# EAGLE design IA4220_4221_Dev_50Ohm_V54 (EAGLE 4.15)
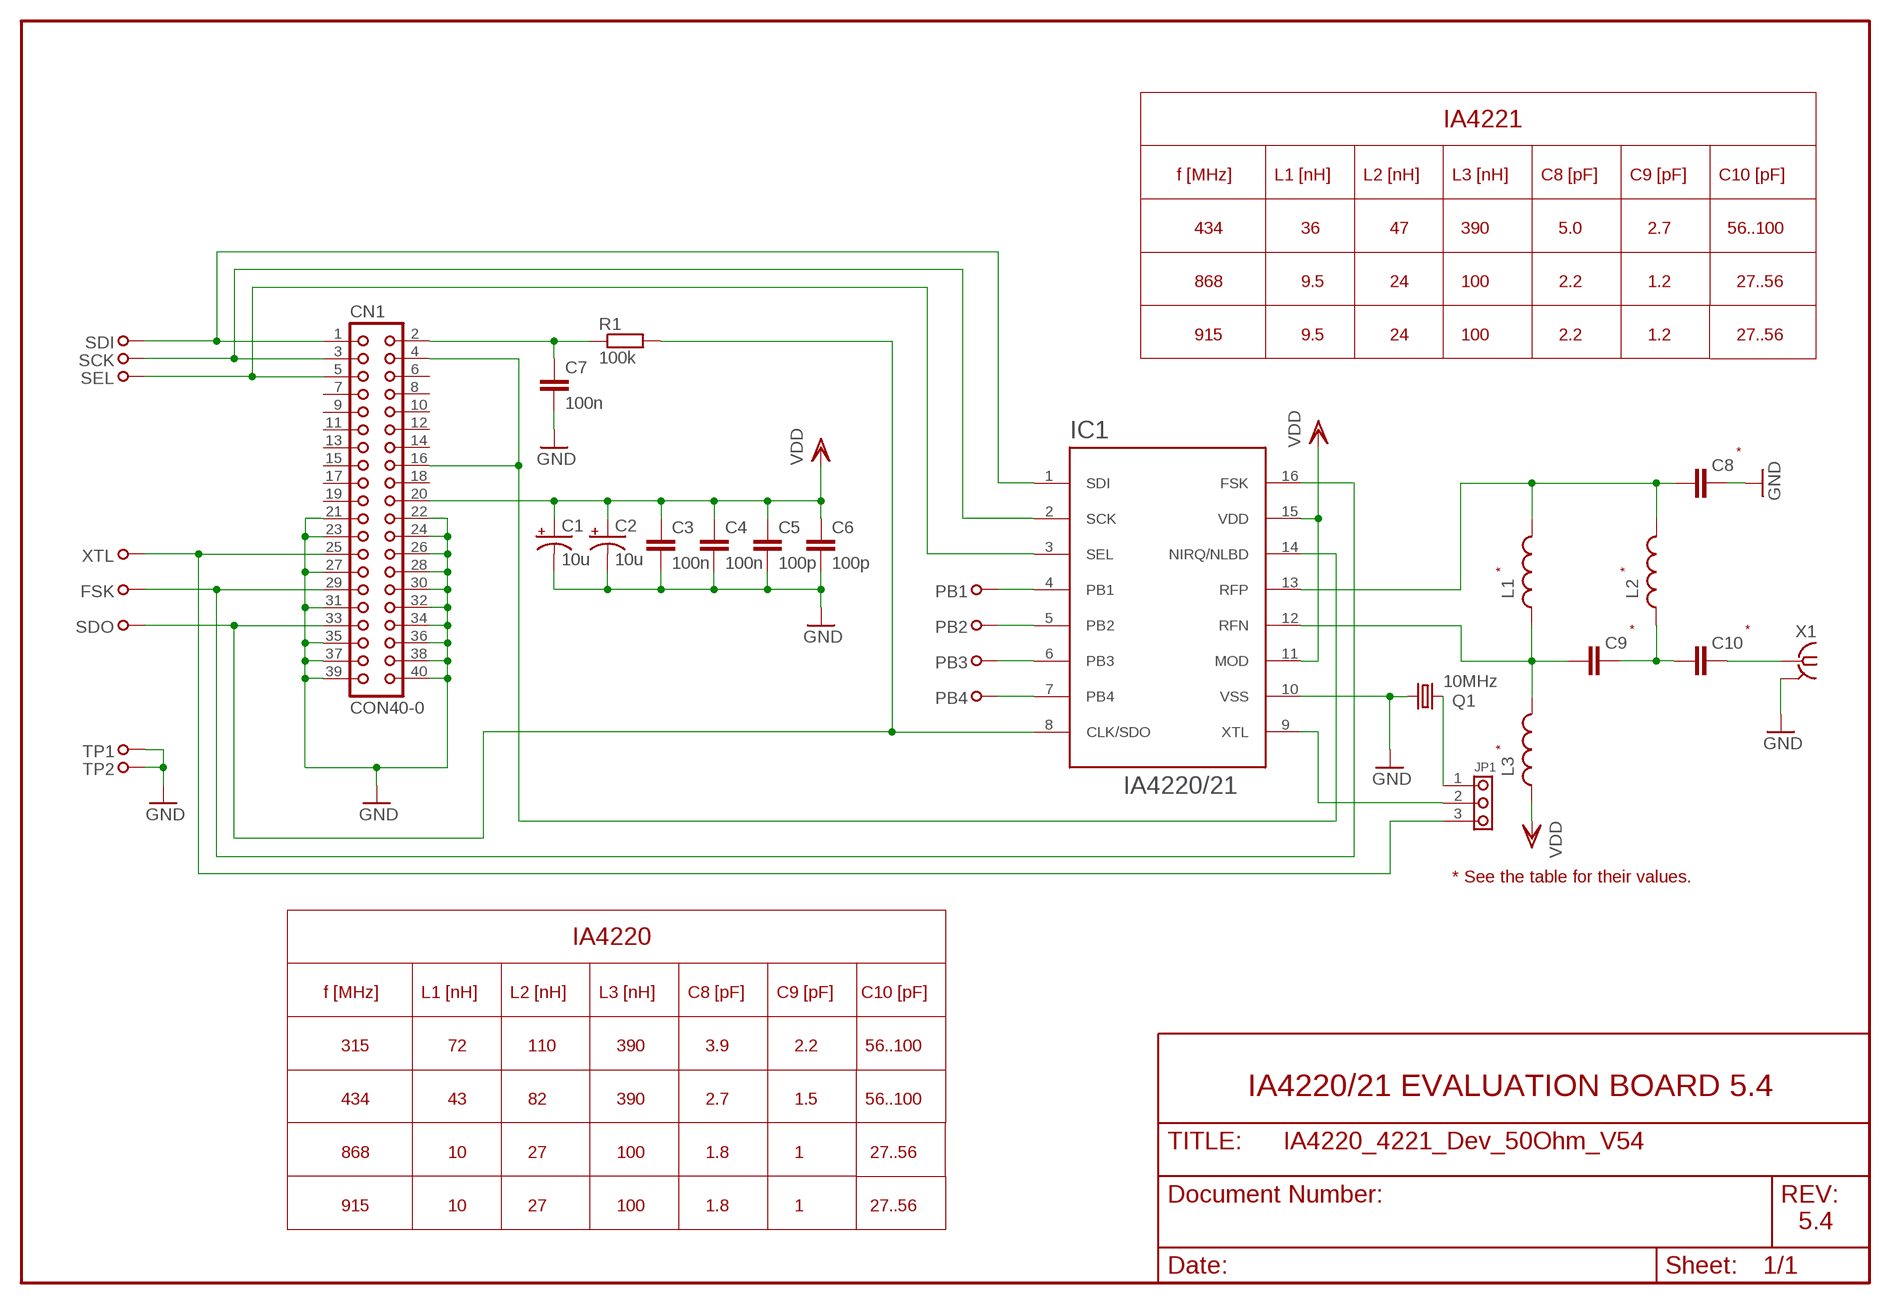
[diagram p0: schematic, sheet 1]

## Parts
C1  10u  CPOL-USA/3216-18R  [A/3216-18R]
C2  10u  CPOL-USA/3216-18R  [A/3216-18R]
C3  100n  C-EUC0603K  [C0603K]
C4  100n  C-EUC0603K  [C0603K]
C5  100p  C-EUC0603K  [C0603K]
C6  100p  C-EUC0603K  [C0603K]
C7  100n  C-EUC0603K  [C0603K]
C8  C-EUC0603K  [C0603K]
C9  C-EUC0603K  [C0603K]
C10  C-EUC0603K  [C0603K]
CN1  CON40-0  [PANDUIT-057-040-0-INTEGRATION]
FSK  TESTPOINT39MIL  [TESTPOINT1,0]
IC1  IA4220/21  TINA-TSSOPNEW  [TSSOP-16(NEW)]
JP1  JUMPER3  [PIN3]
L1  INDUCTCOILCRAFT-0603  [L1608]
L2  INDUCTCOILCRAFT-0603  [L1608]
L3  INDUCTCOILCRAFT-0603  [L1608]
PB1  TESTPOINT39MIL  [TESTPOINT1,0]
PB2  TESTPOINT39MIL  [TESTPOINT1,0]
PB3  TESTPOINT39MIL  [TESTPOINT1,0]
PB4  TESTPOINT39MIL  [TESTPOINT1,0]
Q1  10MHz  SM49  [SM49]
R1  100k  R-EU_R0603  [R0603]
SCK  TESTPOINT39MIL  [TESTPOINT1,0]
SDI  TESTPOINT39MIL  [TESTPOINT1,0]
SDO  TESTPOINT39MIL  [TESTPOINT1,0]
SEL  TESTPOINT39MIL  [TESTPOINT1,0]
TP1  TESTPOINT39MIL  [TESTPOINT1,0]
TP2  TESTPOINT39MIL  [TESTPOINT1,0]
X1  BU-SMA-H  [BU-SMA-H]
XTL  TESTPOINT39MIL  [TESTPOINT1,0]

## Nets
GND: C1.- C2.- C3.2 C4.2 C5.2 C6.2 C7.2 C8.2 CN1.21 CN1.22 CN1.23 CN1.24 CN1.26 CN1.27 CN1.28 CN1.30 CN1.31 CN1.32 CN1.34 CN1.35 CN1.36 CN1.37 CN1.38 CN1.39 CN1.40 IC1.10(VSS) Q1.2 TP1.1 TP2.1 X1.2(GND)
N$1: CN1.3 IC1.2(SCK) SCK.1
N$2: C8.1 IC1.13(RFP) L1.2 L2.2
N$3: CN1.5 IC1.3(SEL) SEL.1
N$4: CN1.33 IC1.8(CLK/SDO) R1.2 SDO.1
N$5: C7.1 CN1.2 R1.1
N$7: C9.1 IC1.12(RFN) L1.1 L3.2
N$8: IC1.4(PB1) PB1.1
N$9: IC1.5(PB2) PB2.1
N$10: IC1.6(PB3) PB3.1
N$11: C9.2 C10.1 L2.1
N$12: IC1.7(PB4) PB4.1
N$13: C10.2 X1.1
N$14: CN1.1 IC1.1(SDI) SDI.1
N$19: CN1.29 FSK.1 IC1.16(FSK)
N$21: CN1.25 JP1.3 XTL.1
N$24: JP1.1 Q1.1
N$25: IC1.9(XTL) JP1.2
TINA: CN1.4 CN1.16 IC1.14(NIRQ/NLBD)
VDD: C1.+ C2.+ C3.1 C4.1 C5.1 C6.1 CN1.20 IC1.11(MOD) IC1.15(VDD) L3.1
Unconnected: CN1.6 CN1.7 CN1.8 CN1.9 CN1.10 CN1.11 CN1.12 CN1.13 CN1.14 CN1.15 CN1.17 CN1.18 CN1.19

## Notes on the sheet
- IA4221
- f [MHz] | L1 [nH] | L2 [nH] | L3 [nH] | C8 [pF] | C9 [pF] | C10 [pF]
- 434 | 36 | 47 | 390 | 5.0 | 2.7 | 56..100
- 868 | 9.5 | 24 | 100 | 2.2 | 1.2 | 27..56
- 915 | 9.5 | 24 | 100 | 2.2 | 1.2 | 27..56
- *
- * | *
- * | *
- *
- * See the table for their values.
- IA4220
- f [MHz] | L1 [nH] | L2 [nH] | L3 [nH] | C8 [pF] | C9 [pF] | C10 [pF]
- 315 | 72 | 110 | 390 | 3.9 | 2.2 | 56..100
- IA4220/21 EVALUATION BOARD 5.4
- 434 | 43 | 82 | 390 | 2.7 | 1.5 | 56..100
- 868 | 10 | 27 | 100 | 1.8 | 1 | 27..56
- 915 | 10 | 27 | 100 | 1.8 | 1 | 27..56
- 5.4

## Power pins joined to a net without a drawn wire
GND: X1.3(GND) X1.4(GND) X1.5(GND)

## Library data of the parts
C1 C2 = rcl:CPOL-US: POLARIZED CAPACITOR, American symbol
C3-C10 = rcl:C-EU: CAPACITOR, European symbol
CN1 = lve:CON40
FSK PB1-PB4 SCK SDI SDO SEL TP1 TP2 XTL = lve:TESTPOINT
IC1 = lve:TINA-TSSOP
JP1 = lve:JUMPER3
L1-L3 = lve:INDUCT: SUMIDA
Q1 = crystal:SM49: CRYSTAL
R1 = rcl:R-EU_: RESISTOR, European symbol
X1 = con-coax:BU-SMA-H: FEMALE SMA CONNECTOR Radiall distributor RS 193-9325

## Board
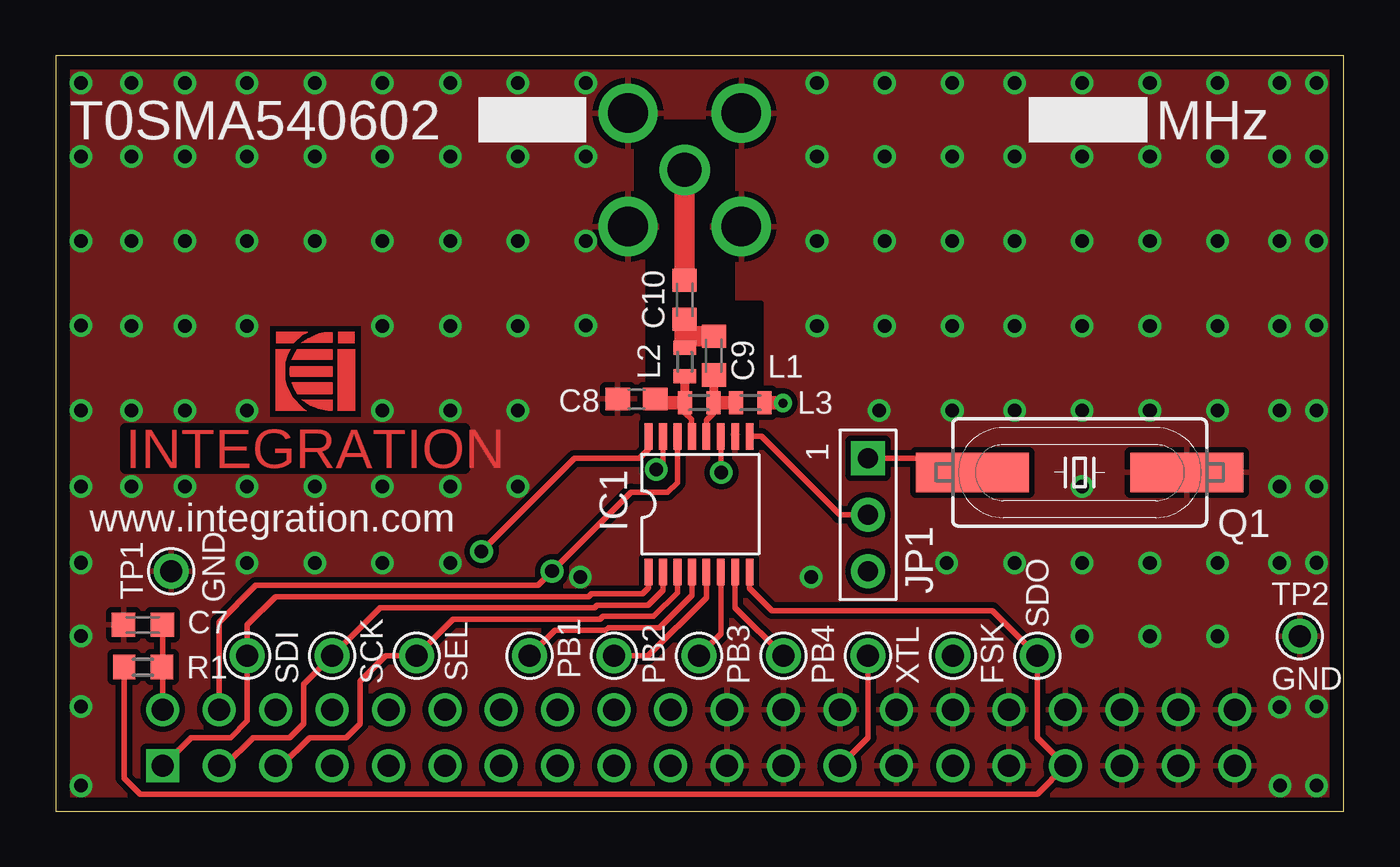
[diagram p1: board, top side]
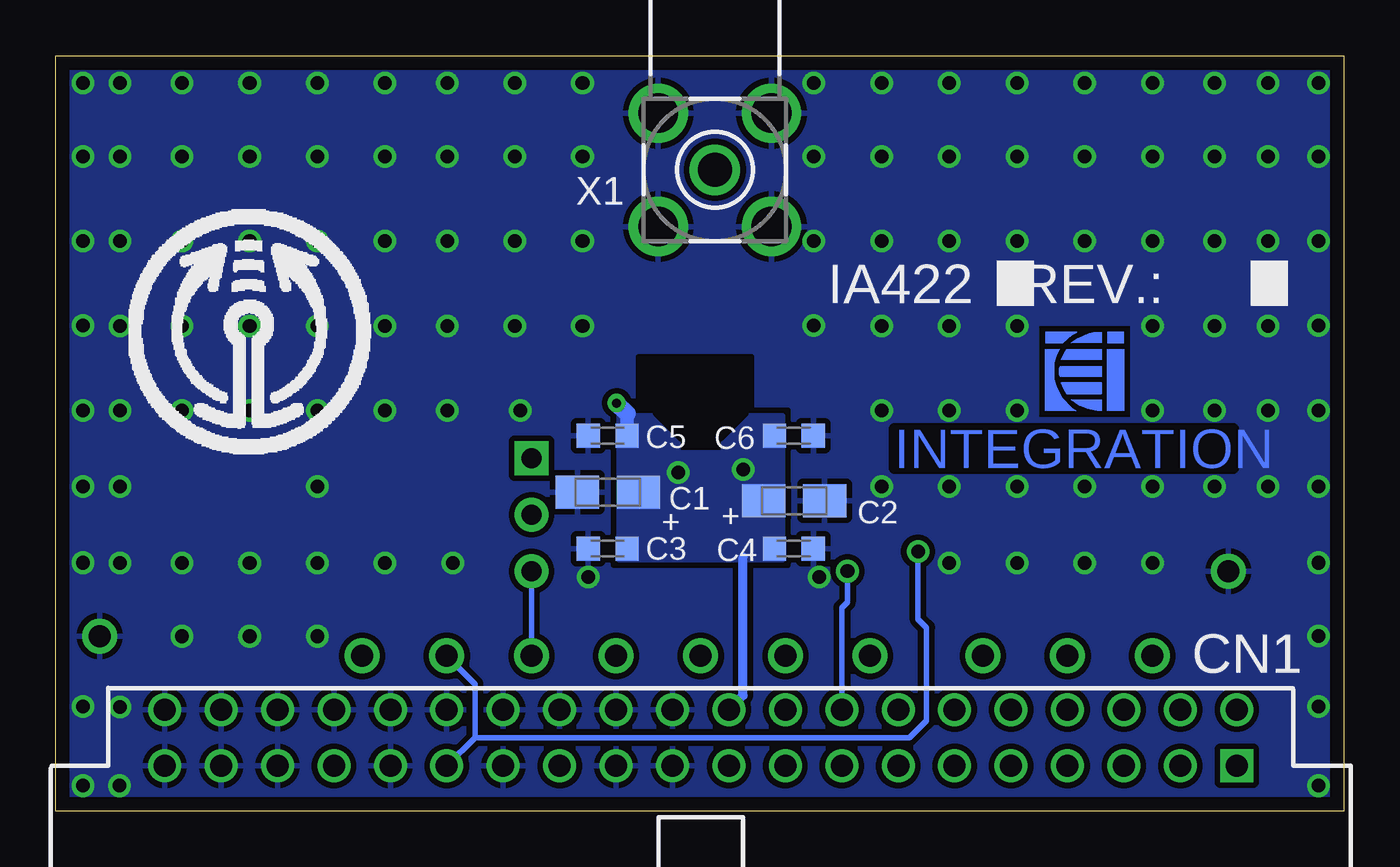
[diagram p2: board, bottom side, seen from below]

Size 58 x 34 mm. Coordinates in mm from the lower left corner, seen from the top.
Outline: 0,0 58,0 58,34 0,34 0,0
Copper layers (1*16): Top 0.035mm / dielectric 1.5mm / Bottom 0.035mm
Design rules "default_INTEGRATION": minimum track width 10mil, minimum drill 20mil, track to track 10mil, track to pad 10mil, pad to pad 10mil, via to via 10mil, smd to smd 10mil, copper to edge 25mil, drill to drill 8mil, minimum pad ring 8mil, minimum via ring 8mil, stop-mask expansion 4mil, vias tented up to drill 35mil, thermal gap 10mil
tRestrict: area 28.1,16.3 to 29.8,17.8; 13 lines
bRestrict: area 28.1,16.3 to 29.8,17.8; 9 lines

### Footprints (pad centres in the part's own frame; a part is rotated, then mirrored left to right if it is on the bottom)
A/3216-18R = smd 1.95 x 1.5: + 1.375,0; - -1.375,0
C0603K = smd 1.05 x 1.08: 1 -0.875,0; 2 0.875,0
C0603 = smd 1.1 x 1: 1 -0.85,0; 2 0.85,0
PANDUIT-057-040-0-INTEGRATION = drill 0.991 square: 1 -24.13,-1.27 | drill 0.991 round: 2 -24.13,-3.81; 3 -21.59,-1.27; 4 -21.59,-3.81; 5 -19.05,-1.27; 6 -19.05,-3.81; 7 -16.51,-1.27; 8 -16.51,-3.81; 9 -13.97,-1.27; 10 -13.97,-3.81; 11 -11.43,-1.27; 12 -11.43,-3.81; 13 -8.89,-1.27; 14 -8.89,-3.81; 15 -6.35,-1.27; 16 -6.35,-3.81; 17 -3.81,-1.27; 18 -3.81,-3.81; 19 -1.27,-1.27; 20 -1.27,-3.81; 21 1.27,-1.27; 22 1.27,-3.81; 23 3.81,-1.27; 24 3.81,-3.81; 25 6.35,-1.27; 26 6.35,-3.81; 27 8.89,-1.27; 28 8.89,-3.81; 29 11.43,-1.27; 30 11.43,-3.81; 31 13.97,-1.27; 32 13.97,-3.81; 33 16.51,-1.27; 34 16.51,-3.81; 35 19.05,-1.27; 36 19.05,-3.81; 37 21.59,-1.27; 38 21.59,-3.81; 39 24.13,-1.27; 40 24.13,-3.81
TESTPOINT1,0 = drill 0.991 pad 1.575 round: 1 0,0
TSSOP-16(NEW) = smd 1.2 x 0.35: 1 -3.107,2.275; 2 -3.107,1.625; 3 -3.107,0.975; 4 -3.107,0.325; 5 -3.107,-0.325; 6 -3.107,-0.975; 7 -3.107,-1.625; 8 -3.107,-2.275; 9 2.993,-2.275; 10 2.993,-1.625; 11 2.993,-0.975; 12 2.993,-0.325; 13 2.993,0.325; 14 2.993,0.975; 15 2.993,1.625; 16 2.993,2.275
PIN3 = drill 0.889 pad 1.524 square: 1 -2.54,0 | drill 0.889 pad 1.524 round: 2 0,0; 3 2.54,0
L1608 = smd 0.64 x 1.02: 1 -0.64,0; 2 0.64,0
SM49 = smd 5.08 x 1.778: 1 -4.826,0; 2 4.826,0
R0603 = smd 1 x 1.1: 1 -0.85,0; 2 0.85,0
BU-SMA-H = drill 1.524 pad 2.286 round: 1 0,0 | drill 1.778 pad 2.667 round: 2 -2.55,2.55; 3 2.55,2.55; 4 2.55,-2.55; 5 -2.55,-2.55

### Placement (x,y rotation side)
C1  33.13,14.35 0 bottom
C2  24.75,13.96 180 bottom
C3  33.15,11.81 180 bottom
C4  24.77,11.81 0 bottom
C5  33.15,16.89 180 bottom
C6  24.77,16.89 0 bottom
C7  3.94,8.38 180 top
C8  [C0603]  26.16,18.55 180 top
C9  29.64,20.49 90 top
C10  28.32,23.01 90 top
CN1  28.96,0.76 180 bottom
FSK  40.39,6.99 90 top
IC1  28.97,13.87 90 top
JP1  36.58,13.34 270 top
L1  28.98,18.37 180 top
L2  28.33,20.21 270 top
L3  31.28,18.37 180 top
PB1  21.34,6.99 90 top
PB2  25.15,6.99 90 top
PB3  28.96,6.99 90 top
PB4  32.77,6.99 90 top
Q1  46.1,15.24 0 top
R1  3.94,6.48 180 top
SCK  12.45,6.99 90 top
SDI  8.64,6.99 90 top
SDO  44.2,6.99 90 top
SEL  16.26,6.99 90 top
TP1  5.21,10.79 90 top
TP2  56.01,7.87 90 top
U$1  [INTEGRATION-HUNGARY]  11.68,19.81 0 top
U$2  [INTEGRATION-HUNGARY]  11.68,19.81 0 bottom
U$3  [TRANSMIT-ICON06]  49.3,21.87 0 bottom
X1  28.32,28.85 90 bottom
XTL  36.58,6.99 90 top

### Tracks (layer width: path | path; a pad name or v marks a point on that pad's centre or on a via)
GND  (via drill 0.61 pad 1.02)
  Top 0.254: IC1.10 30.59,16.89 30.61,16.89 30.59,16.9
  other vias: 3.42,18.03 5.83,18.03 8.62,18.03 14.72,18.03 17.77,18.03 20.81,18.03 3.42,14.6 8.62,11.17 11.67,11.17 14.72,11.17 17.77,11.17 5.83,14.6 8.62,14.6 11.67,14.6 14.72,14.6 55.1,18.03 52.31,18.03 49.26,18.03 46.21,18.03 43.17,18.03 37.07,18.03 40.12,11.17 43.17,11.17 46.21,11.17 49.26,11.17 52.31,11.17 55.1,11.17 55.1,14.6 55.1,4.69 34.02,10.54 46.21,14.6 1.14,18.03 1.14,14.61 1.14,11.18 1.14,4.7 1.14,1.14 56.77,1.14 56.77,4.7 56.77,11.18 56.77,14.61 56.77,18.03 23.62,10.54 55.12,1.14 23.88,25.65 23.88,21.84 55.1,25.65 52.31,25.65 49.26,25.65 46.21,25.65 43.17,25.65 56.77,25.65 55.1,21.84 52.31,21.84 49.26,21.84 46.21,21.84 43.17,21.84 56.77,21.84 3.42,25.65 5.83,25.65 8.62,25.65 11.67,25.65 14.72,25.65 17.77,25.65 20.81,25.65 1.14,25.65 3.42,21.84 5.83,21.84 8.62,21.84 14.72,21.84 17.77,21.84 20.81,21.84 1.14,21.84 17.77,14.6 20.81,14.6 52.31,7.87 49.26,7.87 46.21,7.87 1.14,7.87 23.88,29.46 3.42,29.46 5.83,29.46 8.62,29.46 11.67,29.46 14.72,29.46 17.77,29.46 20.81,29.46 1.14,29.46 55.1,29.46 52.31,29.46 49.26,29.46 46.21,29.46 43.17,29.46 56.77,29.46 40.37,25.65 37.32,25.65 34.28,25.65 40.37,21.84 37.32,21.84 34.28,21.84 40.37,29.46 37.32,29.46 34.28,29.46 40.37,18.03 23.88,32.77 55.1,32.76 52.31,32.76 49.26,32.76 46.21,32.76 43.17,32.76 56.77,32.77 3.42,32.76 5.83,32.76 8.62,32.76 11.67,32.76 14.72,32.76 17.77,32.76 20.81,32.76 1.14,32.77 40.37,32.76 37.32,32.76 34.28,32.76
  pour Top (rank 2): 0.13,0.13 57.78,0.13 57.78,33.78 0.13,33.78
  pour Bottom (rank 2): 0.13,0.13 57.78,0.13 57.78,33.78 0.13,33.78
N$1
  Top 0.254: IC1.2 27.34,9.95 26.67,9.27 24.38,9.27 24.26,9.14 14.61,9.14 SCK.1 11.18,5.71 11.18,3.94 10.54,3.3 8.89,3.3 7.62,2.03 CN1.3
N$2
  Top 0.254: L1.2 28.34,17.91 28.62,17.62 28.62,17.21 IC1.13
  Top 0.406: L1.2 28.34,19.66 L2.2
  Top 0.61: C8.1 27.1,18.55 27.28,18.37 L1.2
N$3
  Top 0.254: IC1.3 28,9.83 26.92,8.76 24.64,8.76 24.51,8.64 17.91,8.64 SEL.1 14.86,6.99 13.72,5.84 13.72,3.94 13.08,3.3 11.43,3.3 10.16,2.03 CN1.5
N$4
  Top 0.254: R1.2 3.09,1.49 3.81,0.76 44.2,0.76 CN1.33 44.2,3.3 SDO.1 42.16,9.02 32.26,9.02 31.25,10.03 IC1.8
N$5
  Top 0.254: CN1.2 4.83,6.48 | C7.1 4.83,8.38 4.83,6.48 | 4.83,6.48 R1.1
N$7
  Top 0.254: L1.1 29.62,17.9 29.31,17.59 29.31,17.27 IC1.12
  Top 0.406: 29.69,18.37 29.66,18.34 L1.1 29.62,18.35 | 29.62,18.35 29.61,18.34 | C9.1 29.64,18.38 29.62,18.35
  Top 0.61: 29.69,18.37 L3.2
N$8
  Top 0.254: IC1.4 28.64,9.72 27.18,8.26 24.89,8.26 24.77,8.13 22.48,8.13 PB1.1
N$9
  Top 0.254: IC1.5 29.3,9.61 26.67,6.99 PB2.1
N$10
  Top 0.254: IC1.6 29.95,7.97 PB3.1
N$11
  Top 0.406: L2.1 28.32,21.18
  Top 0.92: C9.2 | C9.2 | 28.32,21.18 28.32,21.36 | 28.32,21.36 C9.2 | 28.32,21.36 C10.1
N$12
  Top 0.254: IC1.7 30.59,9.16 PB4.1
N$13
  Top 0.92: C10.2 X1.1
N$14
  Top 0.254: IC1.1 26.7,10.06 26.42,9.78 24.13,9.78 24,9.65 9.91,9.65 8.64,8.38 SDI.1 8.64,4.06 7.87,3.3 6.1,3.3 CN1.1
N$19  (via drill 0.61)
  Top 0.254: IC1.16 26.7,16.28 26.29,15.88 23.37,15.88 v19.18,11.68
  Bottom 0.254: 39.12,3.3 19.56,3.3 18.8,4.06 18.8,8.26 19.18,8.64 v19.18,11.68 | 39.12,3.3 CN1.29 | 39.12,3.3 39.12,5.71 FSK.1
N$21
  Top 0.254: CN1.25 36.58,3.3 XTL.1
  Bottom 0.254: XTL.1 JP1.3
N$24
  Top 0.254: Q1.1 40.64,15.88 JP1.1
N$25
  Top 0.254: IC1.9 31.78,16.86 35.31,13.34 JP1.2
TINA  (via drill 0.61 pad 1.02)
  Top 0.254: CN1.4 7.37,8.51 9.02,10.16 21.72,10.16 v22.35,10.79 25.91,14.35 27.56,14.35 28,14.79 IC1.14
  Bottom 0.254: v22.35,10.79 22.35,9.4 22.61,9.14 CN1.16
VDD  (via drill 0.41 pad 0.76, 0.61 pad 1.02)
  Top 0.254: IC1.11 29.95,15.27 v29.97,15.24 | IC1.15 27.34,15.66 v27.05,15.37
  Top 0.61: L3.1 32.33,18.37 32.73,18.37 v32.74,18.36
  Bottom 0.406: CN1.20 27.05,5.21 27.05,11.43
  Bottom 0.61: C5.1 32.27,17.9
  Bottom 0.762: 32.27,17.9 v32.74,18.36
  pour Bottom (no thermals): 25.27,11.3 25.27,17.78 32.64,17.78 32.64,11.3

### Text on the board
Top: INTEGRATION
Bottom: INTEGRATION
tPlace: T0SMA540602 | MHz | 1 | www.integration.com | GND | GND
bPlace: IA422 REV.: | + | +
